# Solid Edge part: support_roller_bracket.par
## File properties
Title: Support roller bracket
Author: Abhinav Rai
Template: Normal.par
Last saved by: Cadcim
Revision: 16
Application: Solid Edge
Material: aluminum
Accuracy: 0.99
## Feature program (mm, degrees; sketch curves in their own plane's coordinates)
sketch for "unnamed Protrusion 1" #1 plane through (0, 0, 0) normal (0, -1, 0) x-axis (1, 0, 0)
  circle centre (0, -138.9237) radius 3.81
sketch for "unnamed Protrusion 1" #2 plane through (0, 0, 0) normal (0, -1, 0) x-axis (1, 0, 0)
  line (143.637, -99.9249) -> (-143.637, -99.9249)
  line (-143.637, -99.9249) -> (-143.637, -115.1647)
  line (-143.637, -115.1647) -> (-61.0846, -156.7704)
  line (-61.0846, -156.7704) -> (-61.0846, -162.9363)
  line (-61.0846, -162.9363) -> (61.0846, -162.9363)
  line (61.0846, -156.7704) -> (61.0846, -162.9363)
  line (143.637, -115.1647) -> (61.0846, -156.7704)
  line (143.637, -99.9249) -> (143.637, -115.1647)
  dimension (linear) = 143.637
extrude "unnamed Protrusion 1" add finite 101.6 symmetric
fillet "Round_1" radius 31.75
fillet "Round_2" radius 6.35
sketch for "unnamed Protrusion 2" plane through (0, 0, 67.2512) normal (1, 0, 0) x-axis (0, 1, 0)
  arc centre (-23.4135, -61.792) radius 19.05 from (-23.4135, -42.742) to (-42.405, -60.3002) ccw
  line (-50.8, -167.1761) -> (-42.405, -60.3002)
  line (-50.8, -167.1761) -> (50.8, -167.1761)
  line (45.7777, -60.8928) -> (50.8, -167.1761)
  arc centre (26.749, -61.792) radius 19.05 from (26.749, -42.742) to (45.7777, -60.8928) cw
  line (19.05, -42.742) -> (26.749, -42.742)
  line (19.05, -64.967) -> (19.05, -42.742)
  arc centre (0, -64.967) radius 19.05 from (-19.05, -64.967) to (19.05, -64.967) ccw
  line (-19.05, -42.742) -> (-19.05, -64.967)
  line (-23.4135, -42.742) -> (-19.05, -42.742)
extrude "unnamed Protrusion 2" add to key point symmetric
sketch for "ExtrudedCutout_1" plane through (0, 0, 0) normal (0, -1, 0) x-axis (1, 0, 0)
  line (-128.3193, 24.5092) -> (125.6319, 24.5092)
  line (125.6319, 24.5092) -> (125.6319, -99.9249)
  line (125.6319, -99.9249) -> (-128.3193, -99.9249)
  line (-128.3193, -99.9249) -> (-128.3193, 24.5092)
extrude "ExtrudedCutout_1" cut finite 203.2 symmetric
chamfer "Chamfer_1" setback 5.08
rib "Rib_1"  Thickness = 25.4 mm
mirror "unnamed Mirror 1" of "Rib_1" about plane through (0, 0, 0) normal (1, 0, 0)
rib "unnamed Rib 1"
sketch for "Hole_1" plane through (0.1259, 0, -162.9363) normal (0, 0, -1) x-axis (-1, 0, 0)
  hole centre (0.1259, 0) bore radius 25.4
hole "Hole_1" diameter 50.8 through
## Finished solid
Body 1: solid body, 55 faces, 142 edges, 86 vertices.
  Faces by surface: plane 38, cylinder 17
  Edges by curve: line 106, circle 34, intersection 2
Bounding box of the edges (mm): 379.121 x 101.600 x 187.446, from (-189.5605, -50.8, -162.9363) to (189.5605, 50.8, 24.5092).
Cylindrical faces by radius (mm): R3.81 x2, R6.35 x2, R19.05 x6, R25.4 x1, R31.75 x4, R55.372 x2
Planar faces by outward normal: +x 4, +y 5, +z 5, -x 4, -y 5, -z 1, oblique 14
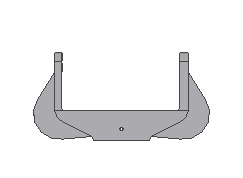
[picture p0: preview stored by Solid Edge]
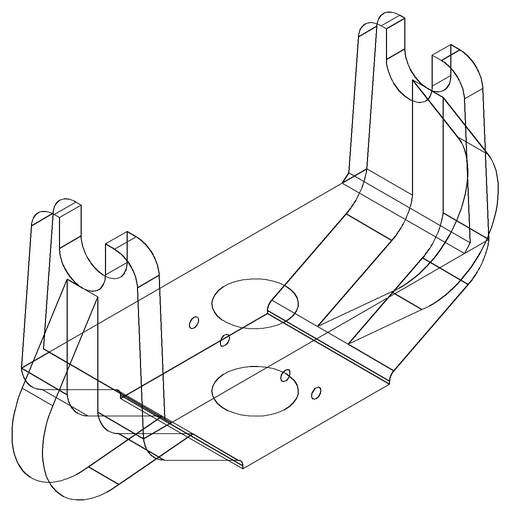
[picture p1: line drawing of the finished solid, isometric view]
